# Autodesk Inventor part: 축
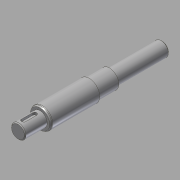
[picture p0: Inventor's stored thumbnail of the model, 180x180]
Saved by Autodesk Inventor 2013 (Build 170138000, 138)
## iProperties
Created: 2019-01
Part Number: 축
Material: 강철, 탄소
Document SubType Name: Modeling
Designer: mduedu
Density: 7.87 g/cm^3
Mass: 452.778 g
Surface Area: 120.904 cm^2
Volume: 57.5322 cm^3
Author: mduedu
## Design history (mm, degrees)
sketch "스케치1"
  geometry: L1 (0, 0)-(26, 0); L2 (26, 0)-(26, 8.5); L3 (26, 8.5)-(0, 8.5); L4 (0, 8.5)-(0, 0); L5 (26, 0)-(84, 0); L6 (84, 0)-(84, 12.5); L7 (84, 12.5)-(26, 12.5); L8 (26, 12.5)-(26, 0); L9 (84, 0)-(108, 0); L10 (108, 0)-(108, 11); L11 (108, 11)-(84, 11); L12 (84, 11)-(84, 0); L13 (108, 0)-(170, 0); L14 (170, 0)-(170, 8.5); L15 (170, 8.5)-(108, 8.5); L16 (108, 8.5)-(108, 0)
  constraints: 32 end point, 8 parallel, 4 horizontal, 4 perpendicular
  dimensions: "d0" = 170 distance between parallel lines of L14 L4; "d2" = 26 distance of L2.end L3.end; "d3" = 24 distance of L10.end L11.end; "d4" = 62 distance of L14.end L15.end; "d5" = 17 diameter of L3 L1; "d6" = 25 diameter of L7 L5; "d7" = 22 diameter of L11 L9; "d8" = 17 diameter of L15 L13
revolve "회전1" sketch "스케치1" stored, may be unused: angle "d9" = 90 deg
node "작업 평면1"
sketch "스케치2" dims "d13" = 18
  geometry: L1 (6.5, -2.5)-(-6.5, -2.5); L2 (-6.5, -2.5)-(-6.5, 2.5); L3 (-6.5, 2.5)-(6.5, 2.5); L4 (6.5, 2.5)-(6.5, -2.5); L5 (13, 8.5)-(13, -8.5) reference; 3 further points
  constraints: 8 end point, 2 midpoint, 2 parallel, 2 vertical alignment, 1 horizontal, 1 horizontal alignment, 1 perpendicular, 4 other
  dimensions: "d10" = 5 distance between parallel lines of L3 L1; "d12" = 4 dimension on L5
extrude "돌출1" cut sketch "스케치2" distance "d14" = 3; taper "d15" = 0 deg
node "작업 평면2"
sketch "스케치3" dims "d19" = 18
  geometry: L1 (-24.5, -2.5)-(-11.5, -2.5); L2 (-11.5, -2.5)-(-11.5, 2.5); L3 (-11.5, 2.5)-(-24.5, 2.5); L4 (-24.5, 2.5)-(-24.5, -2.5); L5 (-31, 8.5)-(-31, -8.5) reference; 3 further points
  constraints: 8 end point, 2 midpoint, 2 parallel, 2 vertical alignment, 1 horizontal, 1 horizontal alignment, 1 perpendicular, 4 other
  dimensions: "d16" = 5 distance between parallel lines of L3 L1; "d18" = 4 dimension on L5
extrude "돌출2" cut sketch "스케치3" distance "d20" = 3; taper "d21" = 0 deg
chamfer "모따기1" distance "d22" = 1; stored, may be unused: second distance "d23" = 2, angle "d24" = 45 deg
chamfer "모따기2" distance "d25" = 2; stored, may be unused: second distance "d26" = 2, angle "d27" = 30 deg
fillet "모깎기2" dims "d30" = 2
node "솔리드1"
